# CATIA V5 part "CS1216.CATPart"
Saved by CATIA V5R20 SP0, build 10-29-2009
Part number: CS1216
Revision: 5
Definition: design
Nomenclature: CS1216
Source: made
Description: NOT SPECIFIED
Bounding box of the stored display mesh (mm): x -15 to 15, y -15 to 15, z -28 to 7.5
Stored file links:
  C:\Users\Raffaele\Desktop\3D X SITO CF\BOLEX\20-TILTED COLUMN SUPPORT\CS1216.CATPart
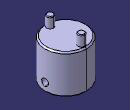
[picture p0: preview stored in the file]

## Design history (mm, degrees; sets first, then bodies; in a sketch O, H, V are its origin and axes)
Body1 "MANIFOLD_SOLID_BREP #691" (main body)
  Solid1: solid without history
